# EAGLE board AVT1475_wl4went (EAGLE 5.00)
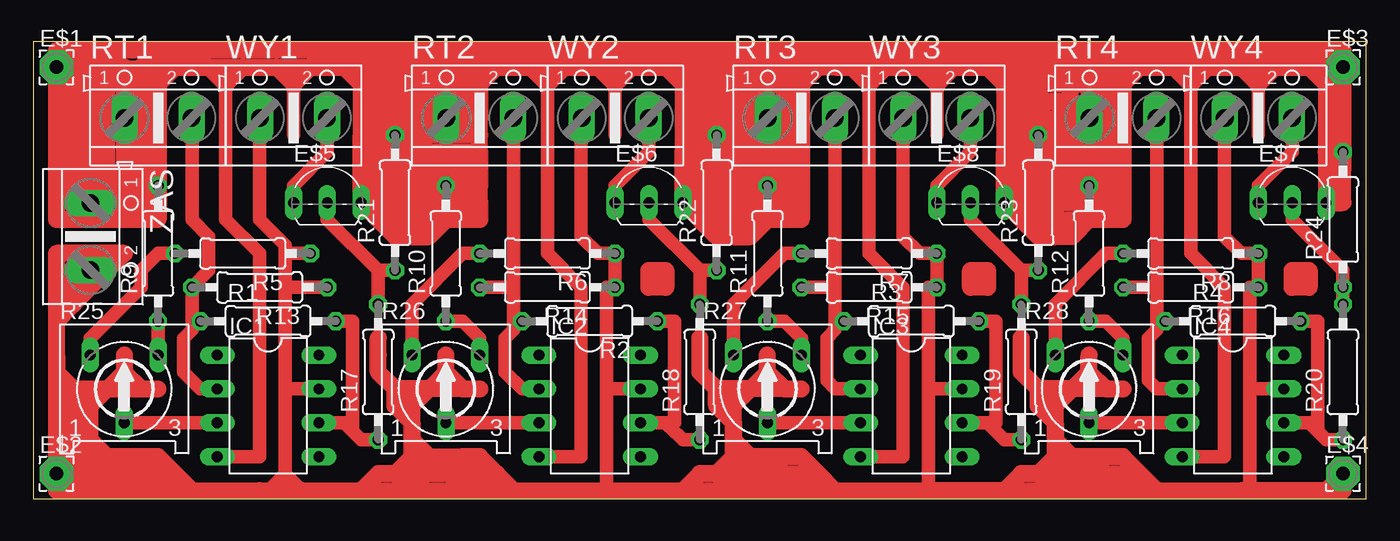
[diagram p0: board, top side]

Size 100 x 34.28 mm. Coordinates in mm from the lower left corner, seen from the top.
Outline: 0,0 100,0 100,34.28 0,34.28 0,0
Copper layers (1*16): Top 0.035mm / dielectric 1.5mm / Bottom 0.035mm
Design rules "default": minimum track width 40mil, minimum drill 24mil, track to track 8mil, track to pad 8mil, pad to pad 8mil, via to via 8mil, smd to smd 8mil, copper to edge 40mil, drill to drill 8mil, minimum pad ring 10mil, minimum via ring 8mil, stop-mask expansion 4mil, vias tented up to drill 0mil, thermal gap 10mil

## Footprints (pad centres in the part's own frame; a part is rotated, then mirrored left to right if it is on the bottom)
2,54/1,0 = drill 1.016 pad 2.54 octagon: 1 0,0
TO92-BCE = drill 0.813 long: B 2.54,0; C 0,0; E -2.54,0
DIL08 = drill 0.813 long: 1 -3.81,-3.81; 2 -1.27,-3.81; 3 1.27,-3.81; 4 3.81,-3.81; 5 3.81,3.81; 6 1.27,3.81; 7 -1.27,3.81; 8 -3.81,3.81
0207/10 = drill 0.813 octagon: 1 -5.08,0; 2 5.08,0
RS3 = drill 0.813 long: A -2.54,2.54; E 2.54,2.54; S 0,-2.54
AK500/2 = drill 1.321 long: 1 -2.515,0; 2 2.515,0

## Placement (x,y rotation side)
E$1  [2,54/1,0]  1.74,32.38 0 top
E$2  [2,54/1,0]  1.74,1.9 0 top
E$3  [2,54/1,0]  98.26,32.38 0 top
E$4  [2,54/1,0]  98.26,1.9 0 top
E$5  [TO92-BCE]  22.06,22.22 0 top
E$6  [TO92-BCE]  46.19,22.22 0 top
E$7  [TO92-BCE]  94.45,22.22 0 top
E$8  [TO92-BCE]  70.32,22.22 0 top
IC1  TL081P  [DIL08]  17.61,6.98 270 top
IC2  TL081P  [DIL08]  41.74,6.98 270 top
IC3  TL081P  [DIL08]  65.88,6.98 270 top
IC4  TL081P  [DIL08]  90,6.98 270 top
R1  [0207/10]  17.61,13.33 0 top
R2  [0207/10]  41.74,13.33 180 top
R3  [0207/10]  65.88,13.33 0 top
R4  [0207/10]  90,13.33 0 top
R5  [0207/10]  15.71,18.41 180 top
R6  [0207/10]  38.57,18.41 180 top
R7  [0207/10]  62.7,18.41 180 top
R8  [0207/10]  86.83,18.41 180 top
R9  [0207/10]  9.36,18.41 90 top
R10  [0207/10]  30.95,18.41 90 top
R11  [0207/10]  55.08,18.41 90 top
R12  [0207/10]  79.21,18.41 90 top
R13  [0207/10]  16.98,15.87 180 top
R14  [0207/10]  38.57,15.87 180 top
R15  [0207/10]  62.7,15.87 180 top
R16  [0207/10]  86.83,15.87 180 top
R17  [0207/10]  25.87,9.52 90 top
R18  [0207/10]  50,9.52 90 top
R19  [0207/10]  74.13,9.52 90 top
R20  [0207/10]  98.26,9.52 90 top
R21  [0207/10]  27.14,22.22 90 top
R22  [0207/10]  51.27,22.22 90 top
R23  [0207/10]  75.4,22.22 90 top
R24  [0207/10]  98.26,20.95 90 top
R25  [RS3]  6.82,8.25 0 top
R26  [RS3]  30.95,8.25 0 top
R27  [RS3]  55.08,8.25 0 top
R28  [RS3]  79.21,8.25 0 top
RT1  [AK500/2]  9.36,28.57 0 top
RT2  [AK500/2]  33.49,28.57 0 top
RT3  [AK500/2]  57.62,28.57 0 top
RT4  [AK500/2]  81.75,28.57 0 top
WY1  [AK500/2]  19.52,28.57 0 top
WY2  [AK500/2]  43.65,28.57 0 top
WY3  [AK500/2]  67.78,28.57 0 top
WY4  [AK500/2]  91.91,28.57 0 top
ZAS  [AK500/2]  4.28,19.68 270 top

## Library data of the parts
E$1-E$4 = wirepad
E$5-E$8 = transistor
IC1-IC4 = linear
R1-R24 = rcl
R25-R28 = pot
RT1-RT4 WY1-WY4 ZAS = con-ptr500

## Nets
N$1: IC1.2 R1.1 R13.2 RT1.2
N$2: R9.1 R25.E
N$3: IC1.3 R25.S
N$4: R5.2 R25.A
N$5: IC1.6 R1.2 R17.1
N$6: R17.2 R21.1
N$7: WY1.2
N$8: WY2.2
N$9: R18.2 R22.1
N$10: R10.1 R26.E
N$11: R6.2 R26.A
N$12: R19.2 R23.1
N$13: IC2.3 R26.S
N$14: IC2.2 R14.2 RT2.2
N$15: R11.1 R27.E
N$16: IC2.6 R2.1 R18.1
N$17: R7.2 R27.A
N$18: R12.1 R28.E
N$19: WY3.2
N$20: IC3.6 R3.2 R19.1
N$21: IC3.3 R27.S
N$22: IC3.2 R15.2 RT3.2
N$23: R8.2 R28.A
N$24: WY4.2
N$25: R20.2 R24.1
N$28: E$5.B E$6.B E$7.B E$8.B IC1.4 IC2.4 IC3.4 IC4.4 R9.2 R10.2 R11.2 R12.2 R21.2 R22.2 R23.2 R24.2 RT1.1 RT2.1 RT3.1 RT4.1 ZAS.1
N$29: IC4.3 R28.S
N$30: IC4.2 R16.2 RT4.2
N$32: IC4.6 R4.2 R20.1
N$33: E$4.1 IC1.7 IC2.7 IC3.7 IC4.7 R5.1 R6.1 R7.1 R8.1 R13.1 R14.1 R15.1 R16.1 WY1.1 WY2.1 WY3.1 WY4.1 ZAS.2

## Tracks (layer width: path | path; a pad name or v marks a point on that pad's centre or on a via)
N$1
  Top 1.016: 11.9,13.33 11.9,12.7 11.27,12.06 11.27,9.52 12.54,8.25 IC1.2 | 11.9,13.33 R13.2 13.17,17.14 13.17,19.68 11.9,20.95 11.9,28.57 RT1.2 | R1.1 11.9,13.33
N$2
  Top 1.016: R25.E R9.1
N$3
  Top 1.016: R25.S IC1.3
N$4
  Top 1.016: R5.2 9.36,18.41 8.09,17.14 8.09,15.87 4.28,12.06 R25.A
N$5
  Top 1.016: R17.1 24.6,4.44 23.65,5.39 | 23.65,5.39 23.33,5.71 IC1.6 | 23.65,5.39 23.96,5.39 23.96,13.33 R1.2
N$6
  Top 1.016: 25.87,17.14 R17.2 | R21.1 25.87,17.14 | 25.87,17.14 22.06,20.95 22.06,22.86
N$7
  Top 1.016: 19.52,22.22 19.52,23.49 22.06,26.03 WY1.2
N$8
  Top 1.016: 43.65,22.22 43.65,23.49 46.19,26.03 46.19,27.3 WY2.2
N$9
  Top 1.016: R18.2 50,17.14 | R22.1 50,17.14 | 50,17.14 46.19,20.95 46.19,22.86
N$10
  Top 1.016: R10.1 32.22,13.33 33.49,12.06 R26.E
N$11
  Top 1.016: R6.2 32.22,18.41 28.41,14.6 R26.A
N$12
  Top 1.016: R19.2 74.13,17.14 | R23.1 74.13,17.14 | 74.13,17.14 70.32,20.95 70.32,22.86
N$13
  Top 1.016: R26.S IC2.3
N$14
  Top 1.016: 36.03,15.87 R14.2 | IC2.2 36.66,8.25 35.39,9.52 35.39,12.06 36.03,12.7 36.03,15.87 | 36.03,15.87 36.03,27.3 RT2.2
N$15
  Top 1.016: R11.1 56.35,13.33 57.62,12.06 R27.E
N$16
  Top 1.016: 47.78,5.39 47.46,5.71 IC2.6 | 47.78,5.39 48.73,4.44 R18.1 | R2.1 48.09,13.33 48.09,5.71 47.78,5.39
N$17
  Top 1.016: R7.2 56.35,18.41 52.54,14.6 R27.A
N$18
  Top 1.016: R12.1 80.48,13.33 81.75,12.06 R28.E
N$19
  Top 1.016: 67.78,22.22 67.78,23.49 70.32,26.03 70.32,27.3 WY3.2
N$20
  Top 1.016: R19.1 72.86,4.44 71.91,5.39 | 71.91,5.39 71.59,5.71 IC3.6 | R3.2 72.22,13.33 72.22,5.71 71.91,5.39
N$21
  Top 1.016: R27.S IC3.3
N$22
  Top 1.016: 60.16,15.87 R15.2 | IC3.2 60.16,8.25 59.52,8.89 59.52,12.06 60.16,12.7 60.16,15.87 | 60.16,15.87 60.16,27.3 RT3.2
N$23
  Top 1.016: R8.2 80.48,18.41 76.67,14.6 R28.A
N$24
  Top 1.016: 91.91,22.22 91.91,23.49 94.45,26.03 94.45,27.3 WY4.2
N$25
  Top 1.016: R20.2 R24.1 98.26,17.14 94.45,20.95 94.45,22.86
N$28
  Top 1.016: 6.82,31.11 6.82,27.3 9.36,24.76 R9.2 8.09,22.22 ZAS.1 | RT1.1 6.82,32.38 8.09,32.38 9.36,32.38 | IC1.4 16.98,3.17 16.98,18.41 14.44,20.95 14.44,31.11 14.44,32.38 | 19.52,32.38 23.33,32.38 24.6,32.38 | 14.44,32.38 13.17,32.38 | 14.44,32.38 15.71,32.38 | 18.25,32.38 19.52,32.38 | 19.52,32.38 19.52,31.11 19.52,27.3 | RT2.1 30.95,27.3 R10.2 30.95,32.38 25.87,32.38 | 50,32.38 50,31.11 50,29.84 | 25.87,32.38 33.49,32.38 | 37.3,32.38 38.57,32.38 | 38.57,32.38 39.84,32.38 | 43.65,32.38 42.38,32.38 | 43.65,32.38 44.92,32.38 47.46,32.38 48.73,32.38 | 25.87,32.38 25.87,29.84 R21.2 | 38.57,32.38 38.57,31.11 38.57,18.41 41.11,15.87 41.11,3.17 IC2.4 | 43.65,32.38 43.65,31.11 43.65,27.3 | R11.2 55.08,26.03 55.08,27.3 RT3.1 55.08,32.38 | 62.7,32.38 62.7,31.11 62.7,18.41 65.24,15.87 65.24,3.17 IC3.4 | 55.08,32.38 57.62,32.38 50,32.38 | 62.7,32.38 60.16,32.38 63.97,32.38 62.7,32.38 | 67.78,32.38 67.78,31.11 67.78,27.3 | 67.78,32.38 66.51,32.38 69.05,32.38 67.78,32.38 | 79.21,24.76 79.21,27.3 RT4.1 79.21,29.84 79.21,31.11 79.21,32.38 80.48,32.38 81.75,32.38 83.02,32.38 84.29,32.38 | 86.83,32.38 86.83,31.11 86.83,18.41 89.37,15.87 89.37,3.17 IC4.4 | 85.56,32.38 86.83,32.38 | 91.91,32.38 91.91,31.11 91.91,27.3 | 88.1,32.38 86.83,32.38 | 91.91,32.38 90.64,32.38 | 98.26,29.84 98.26,32.38 96.99,32.38 95.72,32.38 | 93.18,32.38 91.91,32.38 | 50,32.38 55.08,32.38 | 72.86,32.38 71.59,32.38
  Top 1.27: 22.06,33.65 61.43,33.65 | 61.43,33.65 96.99,33.65 | 96.99,33.65 98.26,33.65 98.26,29.84 | 96.99,33.65 96.99,32.38 | 96.99,32.38 96.99,26.03 | 98.26,29.84 R24.2 | 96.99,26.03 98.26,24.76 R24.2 | R24.2 96.99,26.03 | 81.75,32.38 81.75,31.11 | 81.75,20.95 80.48,20.95 | 80.48,20.95 79.21,20.95 | 76.67,20.95 79.21,20.95 | 76.67,20.95 75.4,20.95 | 72.86,26.03 75.4,23.49 | 76.67,22.22 75.4,23.49 | 72.86,29.84 72.86,32.38 74.13,32.38 | 72.86,29.84 72.86,26.03 | 75.4,32.38 79.21,32.38 80.48,31.11 80.48,23.49 | 75.4,32.38 74.13,32.38 | 80.48,22.22 80.48,23.49 | 80.48,22.22 77.94,22.22 | 77.94,22.22 76.67,22.22 | 76.67,22.22 75.4,22.22 | 75.4,23.49 75.4,22.22 | 75.4,23.49 R23.2 | 74.13,29.84 R23.2 | 74.13,31.11 74.13,29.84 | 74.13,32.38 74.13,31.11 | 74.13,31.11 75.4,31.11 | 77.94,31.11 75.4,31.11 | 77.94,31.11 79.21,31.11 79.21,24.76 | 79.21,24.76 R12.2 76.67,23.49 | 75.4,23.49 76.67,23.49 | 75.4,26.03 75.4,24.76 | 75.4,24.76 75.4,23.49 | R23.2 75.4,26.03 | R23.2 75.4,29.84 77.94,29.84 77.94,24.76 | 77.94,24.76 76.67,24.76 76.67,26.03 | 76.67,26.03 76.67,28.57 | 75.4,26.03 77.94,22.22 | 75.4,31.11 76.67,20.95 | 77.94,31.11 76.67,26.03 | 81.75,32.38 77.94,31.11 | 81.75,32.38 80.48,22.22 | 80.48,22.22 75.4,24.76 | 72.86,26.03 75.4,24.76 | 80.48,23.49 81.75,20.95 | 77.94,24.76 80.48,20.95 | 98.26,29.84 95.72,32.38 93.18,32.38 91.91,31.11 90.64,32.38 88.1,32.38 86.83,31.11 85.56,32.38 84.29,32.38 | 81.75,31.11 81.75,20.95 | 83.02,32.38 81.75,31.11 | 96.99,32.38 80.48,32.38 | 74.13,29.84 71.59,32.38 69.05,32.38 67.78,31.11 66.51,32.38 63.97,32.38 62.7,31.11 61.43,32.38 61.43,33.65 | 61.43,33.65 60.16,32.38 | 58.89,32.38 57.62,32.38 | 57.62,32.38 57.62,27.3
  Top 1.27: 57.62,27.3 57.62,20.95 | 57.62,20.95 55.08,20.95 | 55.08,20.95 51.27,20.95 | 48.73,26.03 50,24.76 | 50,24.76 52.54,22.22 | 48.73,31.11 48.73,26.03 | 47.46,32.38 48.73,31.11 | 48.73,31.11 50,31.11 56.35,31.11 | 57.62,32.38 56.35,31.11 | 56.35,29.84 56.35,31.11 | 56.35,29.84 56.35,24.76 | 56.35,22.22 55.08,22.22 | 52.54,22.22 55.08,22.22 | 52.54,22.22 51.27,22.22 | 50,24.76 R22.2 | 50,28.57 50,29.84 55.08,29.84 55.08,28.57 50,28.57 | 50,27.3 52.54,27.3 | 52.54,27.3 57.62,27.3 | 57.62,27.3 56.35,26.03 55.08,26.03 R22.2 | R22.2 56.35,24.76 | 56.35,24.76 56.35,23.49 | 57.62,20.95 56.35,22.22 | 56.35,23.49 56.35,22.22 | 48.73,26.03 56.35,23.49 | 44.92,32.38 43.65,31.11 42.38,32.38 39.84,32.38 38.57,31.11 37.3,32.38 34.76,32.38 | 34.76,32.38 33.49,32.38 33.49,31.11 | 33.49,29.84 33.49,28.57 | 33.49,26.03 33.49,27.3 | 33.49,24.76 33.49,23.49 | 33.49,22.22 33.49,20.95 30.95,20.95 | 28.41,20.95 29.68,20.95 | 27.14,23.49 28.41,20.95 | 23.33,32.38 24.6,31.11 | 25.87,29.84 33.49,31.11 | 33.49,31.11 33.49,29.84 | 27.14,29.84 33.49,29.84 | 25.87,29.84 27.14,29.84 | 25.87,24.76 27.14,23.49 | 27.14,23.49 33.49,22.22 | 33.49,22.22 33.49,23.49 | 27.14,23.49 33.49,23.49 | 27.14,24.76 27.14,26.03 | 27.14,28.57 R21.2 | 27.14,29.84 27.14,28.57 | 27.14,28.57 33.49,28.57 | 33.49,27.3 33.49,28.57 | 33.49,27.3 R21.2 | 27.14,26.03 R21.2 | 28.41,26.03 27.14,26.03 | 28.41,26.03 33.49,26.03 | 33.49,26.03 33.49,24.76 | 27.14,24.76 33.49,24.76 | 27.14,23.49 27.14,24.76 | 22.06,33.65 19.52,31.11 18.25,32.38 15.71,32.38 14.44,31.11 13.17,32.38 10.63,32.38 | 10.63,32.38 9.36,32.38 9.36,20.95 | 9.36,20.95 5.55,20.95 | 5.55,20.95 1.74,20.95 1.74,33.65 | 22.06,33.65 9.36,33.65 | 9.36,33.65 1.74,33.65
  Top 1.27: 8.09,32.38 9.36,33.65 | 8.09,31.11 8.09,32.38 | 8.09,31.11 8.09,22.22 | 8.09,22.22 4.28,22.22 | 4.28,22.22 3.01,22.22 3.01,23.49 | 3.01,31.11 3.01,23.49 | 3.01,32.38 6.82,32.38 6.82,31.11 | 6.82,31.11 6.82,23.49 | 9.36,20.95 8.09,22.22 | 3.01,32.38 1.74,33.65 | 3.01,32.38 3.01,31.11 | 5.55,31.11 3.01,31.11 | 5.55,23.49 5.55,31.11 | 5.55,20.95 5.55,23.49 | 6.82,23.49 5.55,23.49 | 8.09,22.22 6.82,23.49 | 6.82,23.49 4.28,23.49 4.28,28.57 | 5.55,31.11 4.28,29.84 | 6.82,31.11 5.55,31.11 | 6.82,31.11 3.01,31.11 | 3.01,31.11 4.28,29.84 | 4.28,29.84 4.28,28.57 | 4.28,28.57 3.01,27.3 3.01,23.49 | 4.28,22.22 3.01,23.49 | 4.28,22.22 8.09,26.03 8.09,31.11 | 10.63,32.38 9.36,31.11 8.09,31.11 | 33.49,31.11 34.76,32.38 | 60.16,32.38 75.4,32.38 | 75.4,32.38 96.99,32.38 | 8.09,32.38 24.6,32.38 | 24.6,32.38 48.73,32.38 50,32.38 | 50,32.38 58.89,32.38 | 60.16,32.38 58.89,32.38 | 58.89,32.38 56.35,29.84 | 56.35,24.76 51.27,24.76 | 50,24.76 51.27,24.76 | 50,27.3 50,24.76 | 50,27.3 50,28.57 | 80.48,22.22 79.21,22.22 79.21,24.76 | 28.41,22.22 28.41,20.95 | 28.41,22.22 28.41,19.68 | 28.41,19.68 30.95,20.95 | 28.41,22.22 29.68,20.95 | 27.14,23.49 28.41,22.22 | 51.27,20.95 52.54,19.68 | 55.08,20.95 53.81,20.95 52.54,19.68 | 75.4,20.95 76.67,19.68 75.4,19.68 | 77.94,19.68 75.4,19.68 | 79.21,20.95 77.94,19.68 | 76.67,22.22 76.67,20.95 | 76.67,22.22 76.67,23.49 | 76.67,20.95 77.94,19.68 | 25.87,29.84 24.6,29.84 24.6,31.11 | 24.6,31.11 25.87,29.84 | 25.87,29.84 25.87,24.76 | 25.87,24.76 27.14,24.76 | 28.41,19.68 27.14,20.95 | 28.41,19.68 29.68,20.95 | 29.68,20.95 30.95,20.95 | 30.95,20.95 32.22,22.22 33.49,22.22 | 28.41,22.22 33.49,22.22 | 28.41,26.03 28.41,22.22 | 28.41,26.03 28.41,28.57 24.6,32.38
  Top 1.27: 24.6,32.38 25.87,32.38 27.14,31.11 33.49,31.11 | 28.41,26.03 33.49,31.11 | 25.87,24.76 24.6,26.03 24.6,27.3 | 24.6,31.11 24.6,27.3 | 27.14,19.68 28.41,19.68 | 27.14,24.76 27.14,22.22 | 27.14,20.95 27.14,19.68 | 50,32.38 50,27.3 | 50,27.3 R22.2 | R22.2 51.27,24.76 | 51.27,24.76 52.54,23.49 53.81,23.49 55.08,22.22 | 56.35,23.49 55.08,22.22 | 55.08,20.95 R11.2 | 55.08,20.95 52.54,19.68 | 51.27,19.68 52.54,19.68 | 51.27,24.76 51.27,22.22 | 51.27,20.95 51.27,19.68 | 75.4,32.38 R23.2 | 75.4,24.76 75.4,22.22 | 75.4,20.95 75.4,19.68 | 27.14,19.68 E$5.B 24.6,23.49 | 24.6,23.49 24.6,27.3 | 24.6,27.3 24.6,24.76 27.14,22.22 | 27.14,22.22 27.14,20.95 | 27.14,20.95 24.6,23.49 | 51.27,19.68 E$6.B 48.73,23.49 | 48.73,23.49 48.73,26.03 | 48.73,26.03 48.73,24.76 51.27,22.22 | 51.27,22.22 51.27,20.95 | 51.27,20.95 48.73,23.49 | 75.4,19.68 E$8.B 72.86,23.49 | 72.86,23.49 72.86,26.03 | 72.86,26.03 72.86,24.76 75.4,22.22 | 75.4,22.22 75.4,20.95 | 75.4,20.95 72.86,23.49 | 96.99,26.03 E$7.B 98.26,22.22 R24.2 | 28.41,19.68 29.68,19.68 30.95,20.95 | 51.27,19.68 53.81,19.68 55.08,20.95 | 56.35,23.49 R11.2 | R11.2 52.54,26.03 | 52.54,22.22 52.54,27.3 | 76.67,22.22 72.86,29.84 | 72.86,29.84 74.13,26.03
N$29
  Top 1.016: R28.S IC4.3
N$30
  Top 1.016: 84.29,15.87 R16.2 | IC4.2 84.29,8.25 83.66,8.89 83.66,12.06 84.29,12.7 84.29,15.87 | 84.29,15.87 84.29,27.3 RT4.2
N$32
  Top 1.016: R20.1 96.99,4.44 96.36,5.08 | 96.36,5.08 95.72,5.71 IC4.6 | R4.2 96.36,13.33 96.36,5.08
N$33
  Top 1.016: 43.02,8.25 43.02,15.87 R14.1 R6.1 42.38,18.41 41.11,19.68 41.11,27.3 WY2.1 | 43.02,8.25 IC2.7 | 18.88,19.05 18.88,15.87 R13.1 | 18.88,8.25 18.88,19.05 | 18.88,19.05 16.98,20.95 16.98,28.57 WY1.1 | 43.02,0.63 43.02,8.25 | 67.14,8.25 67.14,15.87 R15.1 R7.1 66.51,18.41 65.24,19.68 65.24,27.3 WY3.1 | 91.28,8.25 91.28,15.87 R16.1 R8.1 90.64,18.41 89.37,19.68 89.37,27.3 WY4.1 | 67.14,0.63 67.14,8.25 | 67.14,8.25 IC3.7 | 91.28,0.63 91.28,8.25 | 91.28,8.25 IC4.7 | 18.88,19.05 18.88,18.41 R5.1 | 18.88,8.25 IC1.7 | 18.88,0.63 18.88,1.9 | 18.88,1.9 18.88,8.25 | 1.74,8.25 1.74,6.98 | 1.74,14.6 1.74,15.87 3.01,17.14 ZAS.2 | 8.09,0.63 6.82,1.9 | 16.98,0.63 17.61,0.63 18.88,1.9 | 18.88,1.9 20.15,0.63
  Top 1.27: 6.82,18.41 1.74,18.41 1.74,14.6 | 1.74,13.33 1.74,14.6 | 1.74,0.63 6.82,0.63 | 11.9,0.63 8.09,0.63 6.82,0.63 | 27.14,0.63 36.03,0.63 | 72.86,0.63 75.4,0.63 | 83.02,0.63 84.29,0.63 | 96.99,0.63 98.26,0.63 E$4.1 96.99,0.63 | 96.99,0.63 91.28,0.63 | 91.28,0.63 90.64,0.63 | 84.29,0.63 91.28,0.63 | 84.29,0.63 81.75,3.17 80.48,3.17 | 76.67,1.9 77.94,1.9 | 75.4,0.63 76.67,1.9 | 75.4,0.63 83.02,0.63 | 83.02,0.63 81.75,1.9 79.21,1.9 | 77.94,1.9 79.21,1.9 | 77.94,1.9 76.67,3.17 | 76.67,5.71 76.67,6.98 | 76.67,6.98 75.4,6.98 | 76.67,5.71 75.4,6.98 | 76.67,1.9 76.67,3.17 | 76.67,3.17 76.67,5.71 | 3.01,14.6 6.82,18.41 | 1.74,14.6 3.01,14.6 | 1.74,14.6 4.28,17.14 | 4.28,17.14 3.01,17.14 | 6.82,18.41 5.55,17.14 4.28,17.14 | 1.74,13.33 3.01,14.6 | 1.74,8.25 1.74,10.79 | 1.74,10.79 1.74,13.33 | 3.01,1.9 3.01,3.17 | 3.01,3.17 3.01,4.44 | 1.74,8.25 3.01,6.98 | 1.74,0.63 1.74,8.25 | 1.74,0.63 3.01,1.9 | 3.01,1.9 4.28,1.9 | 4.28,1.9 5.55,1.9 | 5.55,1.9 4.28,3.17 | 3.01,4.44 4.28,3.17 | 3.01,4.44 3.01,6.98 | 51.27,0.63 60.16,0.63 | 60.16,0.63 67.14,0.63 72.86,0.63 | 60.16,0.63 58.89,1.9 | 58.89,1.9 57.62,3.17 56.35,3.17 | 53.81,1.9 52.54,3.17 | 52.54,5.71 52.54,6.98 | 52.54,6.98 51.27,6.98 | 52.54,5.71 51.27,6.98 | 52.54,1.9 52.54,3.17 | 52.54,3.17 52.54,5.71 | 51.27,0.63 52.54,1.9 | 52.54,1.9 53.81,1.9 | 53.81,1.9 55.08,1.9 | 55.08,1.9 58.89,1.9 | 48.73,0.63 51.27,0.63 | 48.73,0.63 43.02,0.63 36.03,0.63 | 36.03,0.63 34.76,1.9 | 34.76,1.9 33.49,3.17 | 33.49,3.17 32.22,3.17 30.95,1.9 | 28.41,5.71 28.41,6.98 | 28.41,6.98 27.14,6.98 | 28.41,3.17 28.41,5.71 | 28.41,1.9 28.41,3.17 | 27.14,0.63 28.41,1.9 | 28.41,1.9 29.68,1.9 | 30.95,1.9 34.76,1.9 | 24.6,0.63 27.14,0.63 | 20.15,0.63 18.25,0.63 | 11.9,0.63 16.98,0.63 18.25,0.63
  Top 1.27: 11.9,0.63 10.63,1.9 | 10.63,1.9 9.36,3.17 | 9.36,3.17 8.09,3.17 6.82,1.9 8.09,1.9 | 8.09,1.9 10.63,1.9 | 5.55,1.9 8.09,1.9 | 6.82,0.63 5.55,1.9 | 4.28,1.9 4.28,3.17 | 4.28,3.17 4.28,4.44 | 4.28,4.44 4.28,6.98 | 4.28,6.98 3.01,6.98 | 3.01,6.98 3.01,3.17 | 28.41,5.71 27.14,6.98 | 27.14,6.98 27.14,8.25 | 51.27,6.98 51.27,8.25 | 75.4,6.98 75.4,8.25 | 28.41,6.98 27.14,8.25 | 27.14,8.25 25.87,9.52 | 25.87,9.52 25.87,10.79 | 52.54,6.98 51.27,8.25 | 51.27,8.25 50,9.52 | 50,9.52 50,10.79 | 76.67,6.98 75.4,8.25 | 75.4,8.25 74.13,9.52 74.13,12.06 | 4.28,6.98 6.82,9.52 | 6.82,10.79 6.82,9.52 | 28.41,6.98 30.95,9.52 | 30.95,9.52 30.95,10.79 | 52.54,6.98 55.08,9.52 | 55.08,9.52 55.08,10.79 | 76.67,6.98 79.21,9.52 | 79.21,9.52 79.21,10.79 | 79.21,9.52 80.48,8.25 | 80.48,8.25 81.75,8.25 | 55.08,9.52 56.35,8.25 | 56.35,8.25 57.62,8.25 | 30.95,9.52 32.22,8.25 | 32.22,8.25 33.49,8.25 | 6.82,9.52 8.09,8.25 | 8.09,8.25 9.36,8.25 | 20.15,0.63 24.6,0.63 | 20.15,0.63 18.88,0.63 18.25,0.63 | 79.21,1.9 75.4,1.9 | 75.4,1.9 74.13,1.9 72.86,0.63 | 75.4,1.9 76.67,3.17 | 52.54,1.9 51.27,1.9 | 51.27,1.9 50,1.9 48.73,0.63 | 51.27,1.9 52.54,3.17 | 29.68,1.9 27.14,1.9 | 27.14,1.9 25.87,1.9 24.6,0.63 | 27.14,1.9 28.41,3.17 | 25.87,9.52 25.87,12.06 | 50,9.52 50,12.06 | 1.74,10.79 1.74,9.52 3.01,8.25 | 4.28,6.98 3.01,8.25 | 3.01,8.25 8.09,8.25 | 4.28,3.17 9.36,3.17 | 9.36,3.17 5.55,3.17 4.28,4.44 | 32.22,8.25 27.14,8.25 | 28.41,5.71 28.41,4.44 30.95,1.9 | 30.95,1.9 29.68,1.9 | 29.68,1.9 28.41,3.17 | 28.41,3.17 33.49,3.17 | 56.35,8.25 51.27,8.25 | 52.54,5.71 52.54,4.44 53.81,3.17 | 53.81,3.17 55.08,1.9 | 55.08,1.9 56.35,3.17 | 56.35,3.17 53.81,3.17 | 80.48,8.25 75.4,8.25 | 76.67,5.71 76.67,4.44 77.94,3.17 | 77.94,3.17 79.21,1.9
  Top 1.27: 79.21,1.9 80.48,3.17 | 80.48,3.17 77.94,3.17
S$1
  Top 1.27: 47.46,15.87 46.19,15.87 46.19,17.14 47.46,17.14 47.46,15.87
S$2
  Top 1.27: 71.59,15.87 70.32,15.87 70.32,17.14 71.59,17.14 71.59,15.87
S$3
  Top 1.27: 95.72,15.87 94.45,15.87 94.45,17.14 95.72,17.14 95.72,15.87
